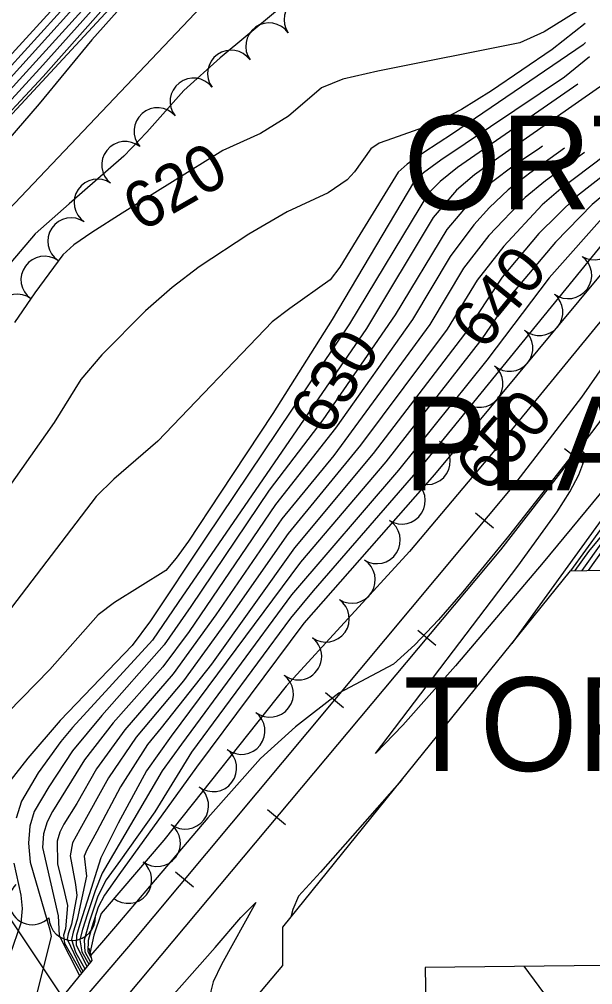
# Model space of a CAD drawing. Extents: x 79600 to 91800, y 75600 to 84400.
# Drawn here: x 85265.8 to 85510.8, y 82448.7 to 82861.2 of the extents above; entities that cross this region are included whole.
import ezdxf

# ---------------------------------------------------------------- set-up
doc = ezdxf.new("R2010")
doc.units = 0
for name, color, linetype in [('084-085$0$TI_ORTHO_CBM', 7, 'Continuous'), ('084-085$0$TI_PLAN', 7, 'Continuous'), ('084-085$0$TI_TOPO', 7, 'Continuous'), ('084-090$0$BLDG', 7, 'Continuous'), ('084-090$0$BRIDGE', 7, 'Continuous'), ('084-090$0$INDEX', 7, 'Continuous'), ('084-090$0$INDXLBL', 7, 'Continuous'), ('084-090$0$INTER', 7, 'Continuous'), ('084-090$0$ROAD', 7, 'Continuous'), ('084-090$0$RR', 7, 'Continuous'), ('084-090$0$TREES', 7, 'Continuous')]:
    doc.layers.add(name, color=color, linetype=linetype)

# ---------------------------------------------------------------- blocks, each defined once
blk = doc.blocks.new('084-090$0$RRTICK100')
blk.add_line((0, -5), (0, 5))

msp = doc.modelspace()

# ---------------------------------------------------------------- linework, layer by layer
at = {"layer": '084-090$0$BLDG'}
msp.add_lwpolyline([(85440.28, 82396.51), (85335.78, 82394.39), (85331.4, 82400.99), (85378.39, 82456.88), (85378.39, 82473.24), (85501.32, 82625.6), (85578.19, 82627.13), (85579.24, 82457.63), (85439.23, 82456.09)], close=True, dxfattribs=at)
at = {"layer": '084-090$0$BRIDGE'}
msp.add_lwpolyline([(85295.42, 82464.24), (85296.7, 82459), (85252.93, 82405.15), (85245.2, 82405.39)], dxfattribs=at)
at = {"layer": '084-090$0$INDEX'}
for points in [[(85333.11, 82909.74), (85275.74, 82846.41), (85246.21, 82813.97), (85233.07, 82800.3), (85207.73, 82776.63), (85144.78, 82725.89), (85140.69, 82722.69), (85138.33, 82721.19), (85133.99, 82720.42), (85130.93, 82721.01), (85127.46, 82723.04), (85120.22, 82731.53), (85115, 82739.16), (85112.84, 82742.9), (85110.54, 82754.2), (85109.34, 82760.34), (85109.18, 82767.15), (85115.25, 82784.69), (85116.33, 82787.45), (85102.66, 82807.94), (85091.12, 82831.85), (85085.36, 82849.88), (85067.69, 82873.61)], [(85631.63, 82905.89), (85600.18, 82856.78), (85568.22, 82808.52), (85535.55, 82761.42), (85515.21, 82733.42), (85469.04, 82677.05), (85432.6, 82633.85), (85379.84, 82576.22), (85327.56, 82510.41), (85303.37, 82482.1), (85300.72, 82479.03), (85297.62, 82469.83), (85295.97, 82461.98)], [(85551.94, 82880.4), (85534.53, 82856.22), (85528.23, 82847.71), (85521.37, 82839.64), (85513.69, 82832.31), (85470.76, 82802.19), (85460.32, 82794.72), (85452.63, 82788.26), (85442.62, 82776.55), (85414.18, 82729.1), (85333.69, 82612.07), (85322.68, 82595.98), (85288.46, 82558.57), (85283.45, 82552.55), (85273.9, 82539.26), (85266.72, 82527.11), (85264.46, 82519.78)], [(85574.14, 82872.14), (85550.44, 82836.82), (85531.92, 82810.32), (85525.28, 82802.17), (85503.92, 82785.47), (85487.87, 82769.71), (85472.12, 82751.03), (85456.05, 82726.73), (85417.05, 82675.72), (85383.33, 82635.41), (85347.85, 82585.65), (85326.44, 82558.44), (85320.59, 82551.31), (85308.96, 82533.17), (85298.97, 82514.17), (85294.67, 82506.33), (85293.55, 82503.55), (85294.45, 82494.99), (85290.5, 82476.59), (85288.75, 82471.05), (85288.03, 82468), (85289.81, 82462.52), (85293.81, 82455.45)], [(85508.85, 82867.61), (85490.09, 82855.83), (85479.71, 82851.12), (85418.96, 82839.12), (85404.03, 82835.6), (85394.92, 82831.93), (85380.82, 82819.85), (85368.88, 82812.43), (85352.81, 82805.22), (85309.79, 82778.43), (85296.79, 82770.09), (85289.01, 82764.81), (85284.4, 82760.58), (85272.45, 82744.35), (85263.76, 82731.63)], [(85515.04, 82638.01), (85506.24, 82625.7)], [(85263.42, 82500.58), (85266.47, 82486.94), (85266.97, 82481.25), (85266.41, 82474.95), (85261.78, 82461.24)]]:
    msp.add_lwpolyline(points, dxfattribs=at)
at = {"layer": '084-090$0$INTER'}
for points in [[(85819.31, 83306.19), (85818.62, 83305.47), (85772.35, 83212.99), (85689.69, 83055.61), (85655.3, 82991.85), (85619.69, 82930.39), (85580.88, 82865.8), (85545.81, 82812.7), (85529.92, 82790.12), (85517.18, 82778.78), (85492.2, 82750.81), (85465.53, 82715.61), (85427.84, 82668.53), (85382.11, 82615.22), (85335.09, 82551.5), (85326.89, 82540), (85301.15, 82496.28), (85298.16, 82488.84), (85294.93, 82479.01), (85292.78, 82472.22), (85291.64, 82467.79), (85292.47, 82462.69), (85295.43, 82457.44)], [(85821.42, 83304.42), (85812.42, 83283.05), (85792.68, 83242.83), (85658.52, 82989.72), (85616.87, 82917.43), (85584.25, 82862.62), (85559.98, 82825.18), (85538.25, 82792.73), (85529.43, 82780.48), (85518.12, 82769.15), (85437.92, 82670.67), (85391.36, 82616.95), (85381.62, 82605.35), (85339.44, 82548.09), (85323.65, 82522.61), (85308.97, 82501.83), (85302.88, 82493.44), (85299.36, 82486.53), (85295.74, 82475.81), (85293.45, 82467.68), (85293.79, 82462.78), (85296.16, 82458.33)], [(85307.15, 82886.4), (85258.03, 82831.86), (85242.51, 82814.76), (85231.47, 82803.62), (85203.33, 82779.43), (85185.73, 82767.36), (85182.21, 82765.37), (85179.78, 82764.96), (85154.54, 82783.79), (85140.05, 82794.75), (85116.87, 82824.23), (85111.51, 82831.74), (85100.64, 82854.68), (85081.68, 82872.27), (85076.03, 82877.47), (85073.03, 82880.91), (85072.68, 82883.58), (85083.56, 82898.85), (85154.58, 82980.91), (85165.35, 82993.95)], [(85302.87, 82886.23), (85260.94, 82839.98), (85238.81, 82815.54), (85229.87, 82806.94), (85218.37, 82797.71), (85209.43, 82790.73), (85203.49, 82787.34), (85199.55, 82785.97), (85194.2, 82785.52), (85187.45, 82787.34), (85179.5, 82792.28), (85163.97, 82806.28), (85151.31, 82820.48), (85134.42, 82832.16), (85122.57, 82842.95), (85113.79, 82848.51), (85086.18, 82874.22), (85081.79, 82878.85), (85079.55, 82882.51), (85079.41, 82885.72), (85084.02, 82893.88), (85125.64, 82944.11), (85151.79, 82973.12), (85165.07, 82988.73)], [(85329.49, 82901.83), (85275.82, 82841.64), (85241.89, 82804.55)], [(85333.09, 82901.32), (85275.9, 82836.86), (85200.97, 82756.4)], [(85298.59, 82886.06), (85250.51, 82833.4), (85235.22, 82816.41), (85228.88, 82810.66), (85221.07, 82806.51), (85209.01, 82802.55), (85204.02, 82801.16), (85201.05, 82800.68), (85179.4, 82826.61), (85170.58, 82836.97), (85156.66, 82850.32), (85151.9, 82853.85), (85148.49, 82855.92), (85145.65, 82856.7), (85133.38, 82852.99), (85128.51, 82851.57), (85124.16, 82851.15), (85120.38, 82851.74), (85114.23, 82855.36), (85099.11, 82868.58)], [(85607.32, 82886.62), (85587.17, 82854.1), (85541.95, 82787.7), (85531.61, 82772.99), (85443.18, 82666.7), (85387.31, 82603.15), (85341.57, 82541.7), (85308.37, 82495.67), (85302.12, 82486.98), (85299.54, 82481.83), (85296.8, 82473.31), (85295.26, 82467.57), (85295.12, 82462.86), (85296.34, 82460.46)], [(85320.8, 82879.48), (85296.76, 82852.41), (85274.2, 82825.06), (85260.91, 82809.6)], [(85577.51, 82868.97), (85553.62, 82832.94), (85534.03, 82804.46), (85527.6, 82796.14), (85510.55, 82782.13), (85494.92, 82766), (85478.02, 82745.93), (85463.46, 82724.67), (85422.45, 82672.13), (85386, 82629.26), (85330.74, 82554.92), (85320.14, 82540.13), (85308.04, 82517.71), (85300.62, 82502.9), (85294.8, 82484.34), (85291.66, 82474.48), (85290.19, 82469.66), (85290.02, 82465.76), (85294.61, 82456.43)], [(85375.25, 82864.46), (85351.56, 82844.75), (85336.07, 82830.79), (85320.29, 82813.08), (85310.47, 82802.77), (85287.13, 82782.41), (85272.58, 82769.51), (85253.22, 82746.86)], [(85507.62, 82859.41), (85493.51, 82848.33), (85467.66, 82830.63), (85454.71, 82822.74), (85442.93, 82816.58), (85425.25, 82810.24), (85419.6, 82808.26), (85415.98, 82805.86), (85409.02, 82796.1), (85405.85, 82792.61), (85397.72, 82787.06), (85380.32, 82778.92), (85363.82, 82769.37), (85342.58, 82755.5), (85331.07, 82746.66), (85319.71, 82736.65), (85301.1, 82717.92), (85292.1, 82707.29), (85280.68, 82688.94), (85250.18, 82645.78)], [(85507.79, 82851.32), (85506.74, 82850.39), (85450.87, 82812.23), (85438.65, 82804.31), (85431.49, 82799.39), (85427.76, 82795.96), (85411.32, 82769.29), (85402.83, 82755.26), (85398.67, 82749.92), (85381.44, 82737.59), (85373.89, 82731.93), (85324.95, 82681.01), (85306.14, 82664.67), (85298.64, 82657.37), (85262.43, 82609.86)], [(85509.5, 82845.21), (85498.73, 82836.54), (85445.87, 82801.11), (85438.54, 82795.68), (85434.2, 82791.45), (85399.51, 82732.95), (85374.09, 82692.75), (85351.57, 82658.71), (85338.06, 82638.28), (85332.84, 82630.92), (85328.4, 82625.64), (85306.49, 82612.05), (85299.48, 82606.71), (85278.8, 82583.44), (85260.9, 82565.03)], [(85504.44, 82833.52), (85464.13, 82805.54), (85453.1, 82797.91), (85445.59, 82791.97), (85440.65, 82786.93), (85406.84, 82731.03), (85345.42, 82639.51), (85321.86, 82604.15), (85314.06, 82593.57), (85283.18, 82561.64), (85269.47, 82545.47), (85261.75, 82535.66)], [(85489.36, 82807.04), (85488.23, 82806.22), (85477.39, 82798.85), (85467.55, 82791.52), (85459.68, 82784.55), (85448.52, 82771.44), (85426.39, 82734.98), (85395.46, 82690.09), (85372.62, 82660.02), (85339.03, 82610.29), (85327.72, 82593.91), (85301.02, 82563.75), (85288.55, 82548.67), (85278.35, 82533.2), (85272.16, 82522.67), (85270.32, 82516.4), (85269.69, 82509.21), (85270.4, 82501), (85278.81, 82472.11), (85279.34, 82469.33), (85268.77, 82426.95), (85267.6, 82423.21)], [(85498.75, 82806.13), (85484.03, 82795.5), (85474.77, 82788.33), (85466.73, 82780.84), (85459.98, 82773.39), (85449.9, 82759.94), (85433.8, 82732.92), (85400.86, 82686.5), (85375.3, 82653.86), (85338.32, 82599.68), (85327.17, 82584.54), (85305.91, 82560.64), (85293.66, 82544.8), (85279.91, 82522.72), (85277.61, 82518.23), (85276.14, 82513.17), (85275.66, 82507.28), (85282.38, 82478.15), (85282.82, 82469.71), (85291.5, 82452.61)], [(85507.27, 82804.38), (85490.66, 82792.16), (85482, 82785.13), (85466.42, 82768.87), (85455.69, 82754.85), (85441.22, 82730.86), (85400.26, 82674.87), (85377.97, 82647.71), (85349.7, 82606.73), (85331.53, 82581.53), (85310.81, 82557.53), (85298.76, 82540.92), (85290.35, 82526.1), (85284.83, 82517.26), (85283.06, 82513.8), (85281.94, 82509.97), (85282.1, 82500.27), (85285.13, 82488.08), (85286.35, 82482.5), (85285.54, 82472.51), (85284.69, 82469.82), (85285.09, 82466.37), (85292.32, 82453.62)], [(85515.91, 82802.87), (85497.29, 82788.82), (85489.22, 82781.93), (85472.87, 82764.35), (85461.49, 82749.77), (85448.63, 82728.79), (85411.65, 82679.31), (85380.65, 82641.56), (85355.03, 82604.95), (85335.9, 82578.52), (85315.7, 82554.42), (85303.86, 82537.05), (85291.71, 82515.02), (85288.5, 82509.36), (85287.51, 82503.73), (85289.79, 82491.54), (85290.33, 82486.84), (85288.02, 82474.55), (85286.72, 82470.43), (85286.22, 82468.11), (85291.79, 82456.42), (85292.99, 82454.44)], [(85821.84, 82762.55), (85808.28, 82749.36), (85799.6, 82741.3), (85790.66, 82735.21), (85747.83, 82716.15), (85741.83, 82712.91), (85736.45, 82710.41), (85731.76, 82709.1), (85640.21, 82707.56), (85606.2, 82708.22), (85595.65, 82708.34), (85589.22, 82708.12), (85585.27, 82707.37), (85574.95, 82703.35), (85566.96, 82699.33), (85558.23, 82693.22), (85549.74, 82684.89), (85532.27, 82661.29), (85530.58, 82658.91), (85527.65, 82657.89), (85520.59, 82652.09), (85501.38, 82625.6)], [(85667.88, 82758.73), (85657.98, 82745.98), (85641.74, 82727.91), (85628.41, 82717.64), (85617.75, 82713.66), (85589.73, 82713.12), (85584.7, 82712.63), (85574.4, 82708.72), (85565.71, 82704.35), (85556.09, 82697.62), (85546.73, 82688.44), (85527.44, 82663.1), (85524.11, 82660.64), (85476.22, 82594.49)], [(85559.09, 82713.05), (85489.7, 82629.11), (85452.14, 82585), (85429.66, 82559.54), (85418.04, 82547.48), (85478.79, 82627.48), (85495.69, 82650.8), (85501.01, 82659.31), (85504.9, 82666.59), (85507.04, 82672.27), (85507.21, 82675.92), (85505.5, 82677.02), (85502.09, 82675.02), (85474.8, 82640.37), (85455.38, 82616.59), (85445.01, 82604.61), (85434.89, 82593.88), (85425.68, 82585.72), (85402.3, 82573.28), (85383.78, 82558.84), (85368.83, 82545.39), (85346.41, 82520), (85319.85, 82488.82), (85307.7, 82474.56), (85300.87, 82466.56), (85296.19, 82461.08)], [(85864.88, 82715.99), (85853.79, 82701.59), (85845.15, 82694.08), (85839.58, 82690.43), (85834.83, 82687.62), (85831.77, 82686.12), (85810.01, 82687.99), (85771.61, 82699.11), (85760.72, 82701.5), (85723.92, 82703.19), (85676.14, 82704.29), (85606.03, 82703.8), (85596.21, 82703.72), (85589.86, 82703.19), (85581.41, 82700.43), (85568.21, 82694.3), (85560.36, 82688.81), (85552.75, 82681.33), (85535.88, 82657.02), (85529.36, 82653.44), (85525.55, 82651.72), (85520.69, 82647.94), (85509.04, 82633.77), (85503.27, 82625.64)], [(85515.15, 82634.53), (85508.93, 82625.75)], [(85429.24, 82536.27), (85394.45, 82496.82), (85385.08, 82486.57), (85382.62, 82480.8), (85381.87, 82477.56)], [(85314.26, 82435.93), (85315.48, 82434.35), (85317.12, 82432.71), (85318.43, 82431.95), (85321.01, 82432.42), (85349.44, 82464.54), (85360.52, 82477.42), (85366.83, 82483.75), (85352.18, 82457.31), (85348.6, 82449.9), (85347.65, 82445.89), (85348.02, 82440.86), (85348.8, 82438.48), (85351.14, 82436.81), (85361.07, 82436.4), (85361.18, 82436.41)], [(85481.46, 82456.55), (85513.41, 82413.2), (85521.63, 82404.21), (85529.78, 82399.2), (85537.3, 82397.19), (85560.98, 82395.31), (85567.09, 82394.36), (85572.57, 82392.82), (85582.62, 82386.48), (85586.26, 82385.75), (85590.08, 82385.98), (85598.59, 82391.18), (85602.69, 82392.95), (85607.79, 82393.82), (85613.53, 82393.04), (85619.76, 82389.21), (85624.58, 82384.2), (85634.59, 82362.47), (85636.51, 82358.12), (85641.59, 82356.72)]]:
    msp.add_lwpolyline(points, dxfattribs=at)
at = {"layer": '084-090$0$ROAD'}
for points in [[(85860.46, 83480.29), (85853.35, 83465.55), (85817.97, 83421.51), (85773.28, 83366.26), (85731.88, 83322), (85677.49, 83264.34), (85609.66, 83191.27), (85538.01, 83114.6), (85468.96, 83041.05), (85400.81, 82969.05), (85352.84, 82918.24), (85257.36, 82815.09), (85202.04, 82758.35), (85143.76, 82703.58), (85135.92, 82699.8), (85127.74, 82699.41), (85118.61, 82701.64), (85111.3, 82707.59), (85098.77, 82725.83), (85029.67, 82828.28), (85000, 82871.03)], [(85449.97, 82978.79), (85218.48, 82734.89), (85182.41, 82698.41), (85163.46, 82677.84), (85156.92, 82667.9), (85151.31, 82657.96), (85150.61, 82650.23), (85152.06, 82644.38), (85155.38, 82636.23), (85284.11, 82443.52)]]:
    msp.add_lwpolyline(points, dxfattribs=at)
at = {"layer": '084-090$0$RR'}
for points in [[(86153.28, 83943.88), (85933.9, 83485.8), (85758.12, 83119.71), (85690.49, 82979.78), (85674.9, 82948.29), (85659.44, 82919.26), (85642.77, 82887.91), (85628.81, 82863.07), (85611.2, 82832.49), (85591.44, 82800.8), (85571.68, 82769.57), (85544.13, 82730.24), (85511.37, 82685.91), (85471.43, 82634.57), (85256.44, 82378.02), (85218.73, 82334.88), (85191.53, 82306.51), (85164.47, 82279.53), (85141.37, 82258.31), (85109.84, 82229.74), (85084.12, 82208.03), (85052.41, 82183.17), (85018.39, 82157.2), (85000, 82144.89)], [(86139.68, 83943.87), (86090.93, 83842.75), (85923.18, 83492.02), (85725.74, 83083.88), (85678.84, 82986.92), (85656.12, 82942.7), (85643.25, 82917.41), (85629, 82890.71), (85615.33, 82867.42), (85596.8, 82836.67), (85573.71, 82798.77), (85557.74, 82774.06), (85536.59, 82743.44), (85505.99, 82699.75), (85477.03, 82661.95), (85312.39, 82465.02), (85221.12, 82358.37), (85190.73, 82324.72), (85165.51, 82299.46), (85143.33, 82278.71), (85113.8, 82251.24), (85078.9, 82221.26)]]:
    msp.add_lwpolyline(points, dxfattribs=at)
at = {"layer": '084-090$0$TREES'}
msp.add_line((85306.06, 82485.65), (85306.06, 82485.65), dxfattribs=at)
for centre, start, end in [((85388.95, 82861.13), 34.301, 214.301), ((85372.55, 82849.68), 35.5316, 215.5316), ((85356.27, 82838.05), 35.5322, 215.5322), ((85340.23, 82826.11), 37.814, 217.814), ((85324.79, 82813.42), 41.0283, 221.0283), ((85311.03, 82799.02), 51.5474, 231.5474), ((85299.18, 82782.92), 55.7782, 235.7782), ((85287.94, 82766.38), 55.7782, 235.7782), ((85511.53, 82768.47), 238.5271, 58.5271), ((85276.49, 82749.99), 54.3937, 234.3937), ((85500.41, 82751.87), 233.7869, 53.7869), ((85264.74, 82733.8), 53.6452, 233.6452), ((85488.09, 82736.12), 230.1788, 50.1788), ((85475.29, 82720.76), 230.1788, 50.1788), ((85462.48, 82705.4), 230.1788, 50.1788), ((85450.7, 82689.29), 237.4681, 57.4681), ((85439.97, 82672.4), 237.6975, 57.6975), ((85429.29, 82655.5), 237.6975, 57.6975), ((85418.6, 82638.6), 237.6975, 57.6975), ((85407.91, 82621.69), 237.6975, 57.6975), ((85396.81, 82605.06), 234.8279, 54.8279), ((85385.01, 82588.92), 232.8652, 52.8652), ((85372.92, 82572.99), 232.7324, 52.7324), ((85360.77, 82557.1), 232.4967, 52.4967), ((85348.68, 82541.17), 233.0961, 53.0961), ((85336.68, 82525.17), 233.1223, 53.1223), ((85324.67, 82509.17), 233.1223, 53.1223), ((85312.37, 82493.41), 230.9157, 50.9157), ((85271.36, 82484.32), 134.6066, 314.6066), ((85288.37, 82477.61), 182.315, 2.315)]:
    msp.add_arc(centre, 10, start, end, dxfattribs=at)

# ---------------------------------------------------------------- block references
at = {"layer": '084-090$0$RR'}
for p, rotation in [((85502.74, 82674.81), -127.88093199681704), ((85464.61, 82647.1), -129.8964843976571), ((85439.95, 82597), -129.9633681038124), ((85400.47, 82570.38), -129.8964843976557), ((85375.72, 82520.36), -129.96336810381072), ((85336.33, 82493.66), -129.89648439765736)]:
    msp.add_blockref('084-090$0$RRTICK100', p, dxfattribs=dict(at, rotation=rotation))

# ---------------------------------------------------------------- texts
at = {"layer": '084-085$0$TI_ORTHO_CBM'}
msp.add_text('ORTHOPHOTO / CONTOUR BASE MAP', height=40, dxfattribs=at).set_placement((85430, 82780))
at = {"layer": '084-085$0$TI_PLAN'}
msp.add_text('PLANIMETRIC  MAP', height=40, dxfattribs=at).set_placement((85430, 82660))
at = {"layer": '084-085$0$TI_TOPO'}
msp.add_text('TOPOGRAPHIC  MAP', height=40, dxfattribs=at).set_placement((85430, 82540))
at = {"layer": '084-090$0$INDXLBL'}
for s, rotation, p in [('620', 29.889, (85317.76, 82770.08)), ('640', 50.8152, (85464.16, 82719.09)), ('630', 58.2303, (85397.1, 82682.38)), ('650', 49.017, (85465.66, 82658.12))]:
    msp.add_text(s, height=20, rotation=rotation, dxfattribs=at).set_placement(p)

doc.saveas('drawing.dxf')
